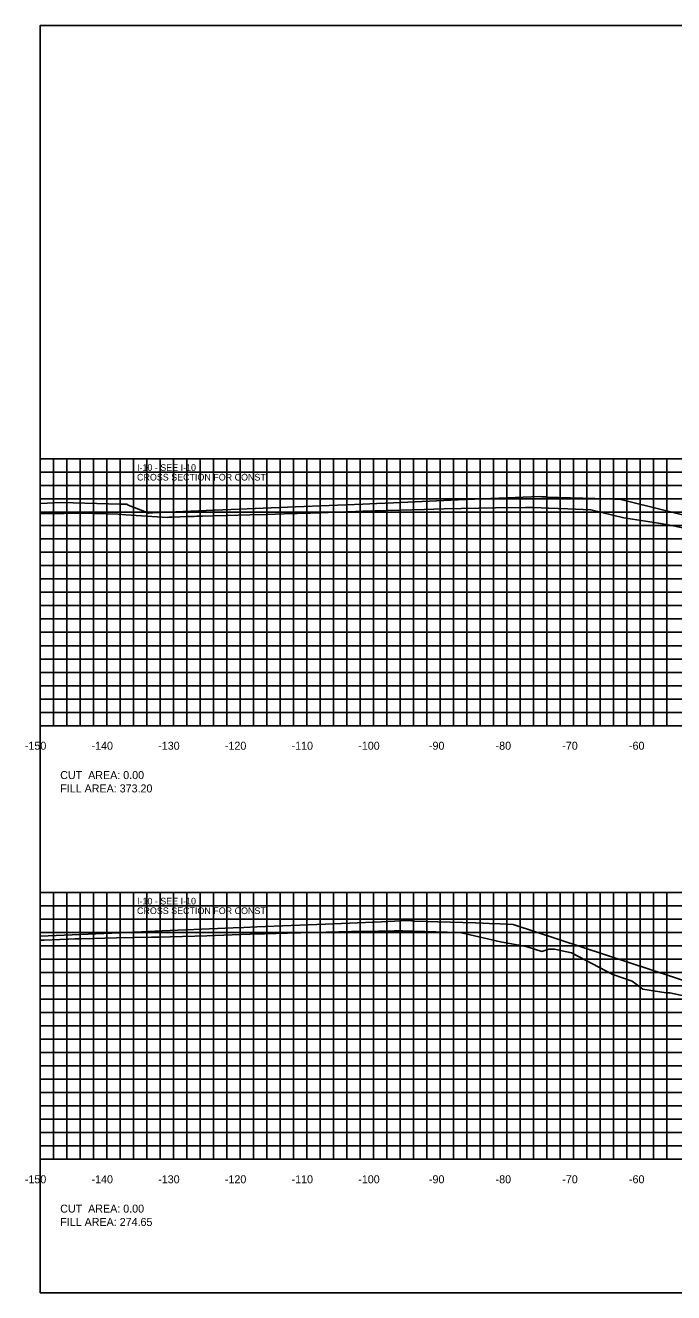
# Model space of a CAD drawing. Extents: x 1797652 to 1804145, y 245981 to 250269.
# Drawn here: x 1802818.8 to 1802916, y 250079.4 to 250269.4 of the extents above; entities that cross this region are included whole.
import ezdxf

# ---------------------------------------------------------------- set-up
doc = ezdxf.new("R2010")
doc.units = 0
for name, color, linetype in [('10', 7, 'Continuous'), ('3', 7, 'Continuous'), ('60', 7, 'Continuous'), ('ANNO-TXT', 7, 'Continuous'), ('CL-CNST', 7, 'Continuous'), ('Level 62', 7, 'Continuous'), ('M-ROADS', 7, 'Continuous')]:
    doc.layers.add(name, color=color, linetype=linetype)

msp = doc.modelspace()

# ---------------------------------------------------------------- linework, layer by layer
msp.add_lwpolyline([(1802821, 250079.43), (1803121, 250079.43), (1803121, 250269.43), (1802821, 250269.43)], close=True)
at = {"layer": '60'}
for p, q in [((1802820.94, 250204.43), (1802821, 250204.43)), ((1802821, 250164.43), (1802821, 250204.43)), ((1802820.94, 250194.43), (1802821, 250194.43)), ((1802820.94, 250184.43), (1802821, 250184.43)), ((1802820.94, 250174.43), (1802821, 250174.43)), ((1802820.94, 250164.43), (1802821, 250164.43)), ((1802821, 250164.43), (1803121, 250164.43)), ((1802821, 250164.37), (1802821, 250164.43)), ((1802831, 250164.37), (1802831, 250164.43)), ((1802841, 250164.37), (1802841, 250164.43)), ((1802851, 250164.37), (1802851, 250164.43)), ((1802861, 250164.37), (1802861, 250164.43)), ((1802871, 250164.37), (1802871, 250164.43)), ((1802881, 250164.37), (1802881, 250164.43)), ((1802891, 250164.37), (1802891, 250164.43)), ((1802901, 250164.37), (1802901, 250164.43)), ((1802911, 250164.37), (1802911, 250164.43)), ((1802820.94, 250139.43), (1802821, 250139.43)), ((1802821, 250099.43), (1802821, 250139.43)), ((1802820.94, 250129.43), (1802821, 250129.43)), ((1802820.94, 250119.43), (1802821, 250119.43)), ((1802820.94, 250109.43), (1802821, 250109.43)), ((1802820.94, 250099.43), (1802821, 250099.43)), ((1802821, 250099.43), (1803121, 250099.43)), ((1802821, 250099.37), (1802821, 250099.43)), ((1802831, 250099.37), (1802831, 250099.43)), ((1802841, 250099.37), (1802841, 250099.43)), ((1802851, 250099.37), (1802851, 250099.43)), ((1802861, 250099.37), (1802861, 250099.43)), ((1802871, 250099.37), (1802871, 250099.43)), ((1802881, 250099.37), (1802881, 250099.43)), ((1802891, 250099.37), (1802891, 250099.43)), ((1802901, 250099.37), (1802901, 250099.43)), ((1802911, 250099.37), (1802911, 250099.43))]:
    msp.add_line(p, q, dxfattribs=at)
at = {"layer": 'CL-CNST'}
for points in [[(1802821, 250197.76), (1802822.02, 250197.81), (1802824.18, 250197.9), (1802833, 250197.66), (1802833.97, 250197.64), (1802834.18, 250197.52), (1802837.3, 250196.32), (1802837.9, 250196.35), (1802845.9, 250196.69), (1802847.08, 250196.74), (1802847.19, 250196.74), (1802859.28, 250197.25), (1802869.39, 250197.67), (1802871.48, 250197.76), (1802873.97, 250197.86), (1802883.68, 250198.27), (1802887.34, 250198.42), (1802895.88, 250198.78), (1802896.25, 250198.76), (1802896.89, 250198.74), (1802896.93, 250198.7), (1802896.95, 250198.68), (1802900.54, 250198.58), (1802906.05, 250198.43), (1802907.18, 250198.39), (1802908.08, 250198.35), (1802928.03, 250193.38)], [(1802821, 250132.88), (1802827, 250133.14), (1802834.09, 250133.44), (1802839.28, 250133.66), (1802849.92, 250134.11), (1802851.54, 250134.17), (1802853.51, 250134.26), (1802863.8, 250134.69), (1802872.2, 250135.05), (1802876.07, 250135.21), (1802876.73, 250135.18), (1802877.09, 250135.17), (1802877.12, 250135.13), (1802877.14, 250135.11), (1802880.65, 250135.02), (1802886.29, 250134.87), (1802887.43, 250134.83), (1802888.33, 250134.79), (1802889.97, 250134.72), (1802891.91, 250134.64), (1802926.35, 250123.32), (1802933.6, 250120.94)]]:
    msp.add_lwpolyline(points, dxfattribs=at)
at = {"layer": 'Level 62'}
for p, q in [((1802821, 250204.43), (1803121, 250204.43)), ((1802821, 250164.43), (1802821, 250204.43)), ((1802823, 250164.43), (1802823, 250204.43)), ((1802825, 250164.43), (1802825, 250204.43)), ((1802827, 250164.43), (1802827, 250204.43)), ((1802829, 250164.43), (1802829, 250204.43)), ((1802831, 250164.43), (1802831, 250204.43)), ((1802833, 250164.43), (1802833, 250204.43)), ((1802835, 250164.43), (1802835, 250204.43)), ((1802837, 250164.43), (1802837, 250204.43)), ((1802839, 250164.43), (1802839, 250204.43)), ((1802841, 250164.43), (1802841, 250204.43)), ((1802843, 250164.43), (1802843, 250204.43)), ((1802845, 250164.43), (1802845, 250204.43)), ((1802847, 250164.43), (1802847, 250204.43)), ((1802849, 250164.43), (1802849, 250204.43)), ((1802851, 250164.43), (1802851, 250204.43)), ((1802853, 250164.43), (1802853, 250204.43)), ((1802855, 250164.43), (1802855, 250204.43)), ((1802857, 250164.43), (1802857, 250204.43)), ((1802859, 250164.43), (1802859, 250204.43)), ((1802861, 250164.43), (1802861, 250204.43)), ((1802863, 250164.43), (1802863, 250204.43)), ((1802865, 250164.43), (1802865, 250204.43)), ((1802867, 250164.43), (1802867, 250204.43)), ((1802869, 250164.43), (1802869, 250204.43)), ((1802871, 250164.43), (1802871, 250204.43)), ((1802873, 250164.43), (1802873, 250204.43)), ((1802875, 250164.43), (1802875, 250204.43)), ((1802877, 250164.43), (1802877, 250204.43)), ((1802879, 250164.43), (1802879, 250204.43)), ((1802881, 250164.43), (1802881, 250204.43)), ((1802883, 250164.43), (1802883, 250204.43)), ((1802885, 250164.43), (1802885, 250204.43)), ((1802887, 250164.43), (1802887, 250204.43)), ((1802889, 250164.43), (1802889, 250204.43)), ((1802891, 250164.43), (1802891, 250204.43)), ((1802893, 250164.43), (1802893, 250204.43)), ((1802895, 250164.43), (1802895, 250204.43)), ((1802897, 250164.43), (1802897, 250204.43)), ((1802899, 250164.43), (1802899, 250204.43)), ((1802901, 250164.43), (1802901, 250204.43)), ((1802903, 250164.43), (1802903, 250204.43)), ((1802905, 250164.43), (1802905, 250204.43)), ((1802907, 250164.43), (1802907, 250204.43)), ((1802909, 250164.43), (1802909, 250204.43)), ((1802911, 250164.43), (1802911, 250204.43)), ((1802913, 250164.43), (1802913, 250204.43)), ((1802915, 250164.43), (1802915, 250204.43)), ((1802821, 250202.43), (1803121, 250202.43)), ((1802821, 250200.43), (1803121, 250200.43)), ((1802821, 250198.43), (1803121, 250198.43)), ((1802821, 250196.43), (1803121, 250196.43)), ((1802821, 250194.43), (1803121, 250194.43)), ((1802821, 250192.43), (1803121, 250192.43)), ((1802821, 250190.43), (1803121, 250190.43)), ((1802821, 250188.43), (1803121, 250188.43)), ((1802821, 250186.43), (1803121, 250186.43)), ((1802821, 250184.43), (1803121, 250184.43)), ((1802821, 250182.43), (1803121, 250182.43)), ((1802821, 250180.43), (1803121, 250180.43)), ((1802821, 250178.43), (1803121, 250178.43)), ((1802821, 250176.43), (1803121, 250176.43)), ((1802821, 250174.43), (1803121, 250174.43)), ((1802821, 250172.43), (1803121, 250172.43)), ((1802821, 250170.43), (1803121, 250170.43)), ((1802821, 250168.43), (1803121, 250168.43)), ((1802821, 250166.43), (1803121, 250166.43)), ((1802821, 250164.43), (1803121, 250164.43)), ((1802821, 250139.43), (1803121, 250139.43)), ((1802821, 250099.43), (1802821, 250139.43)), ((1802823, 250099.43), (1802823, 250139.43)), ((1802825, 250099.43), (1802825, 250139.43)), ((1802827, 250099.43), (1802827, 250139.43)), ((1802829, 250099.43), (1802829, 250139.43)), ((1802831, 250099.43), (1802831, 250139.43)), ((1802833, 250099.43), (1802833, 250139.43)), ((1802835, 250099.43), (1802835, 250139.43)), ((1802837, 250099.43), (1802837, 250139.43)), ((1802839, 250099.43), (1802839, 250139.43)), ((1802841, 250099.43), (1802841, 250139.43)), ((1802843, 250099.43), (1802843, 250139.43)), ((1802845, 250099.43), (1802845, 250139.43)), ((1802847, 250099.43), (1802847, 250139.43)), ((1802849, 250099.43), (1802849, 250139.43)), ((1802851, 250099.43), (1802851, 250139.43)), ((1802853, 250099.43), (1802853, 250139.43)), ((1802855, 250099.43), (1802855, 250139.43)), ((1802857, 250099.43), (1802857, 250139.43)), ((1802859, 250099.43), (1802859, 250139.43)), ((1802861, 250099.43), (1802861, 250139.43)), ((1802863, 250099.43), (1802863, 250139.43)), ((1802865, 250099.43), (1802865, 250139.43)), ((1802867, 250099.43), (1802867, 250139.43)), ((1802869, 250099.43), (1802869, 250139.43)), ((1802871, 250099.43), (1802871, 250139.43)), ((1802873, 250099.43), (1802873, 250139.43)), ((1802875, 250099.43), (1802875, 250139.43)), ((1802877, 250099.43), (1802877, 250139.43)), ((1802879, 250099.43), (1802879, 250139.43)), ((1802881, 250099.43), (1802881, 250139.43)), ((1802883, 250099.43), (1802883, 250139.43)), ((1802885, 250099.43), (1802885, 250139.43)), ((1802887, 250099.43), (1802887, 250139.43)), ((1802889, 250099.43), (1802889, 250139.43)), ((1802891, 250099.43), (1802891, 250139.43)), ((1802893, 250099.43), (1802893, 250139.43)), ((1802895, 250099.43), (1802895, 250139.43)), ((1802897, 250099.43), (1802897, 250139.43)), ((1802899, 250099.43), (1802899, 250139.43)), ((1802901, 250099.43), (1802901, 250139.43)), ((1802903, 250099.43), (1802903, 250139.43)), ((1802905, 250099.43), (1802905, 250139.43)), ((1802907, 250099.43), (1802907, 250139.43)), ((1802909, 250099.43), (1802909, 250139.43)), ((1802911, 250099.43), (1802911, 250139.43)), ((1802913, 250099.43), (1802913, 250139.43)), ((1802915, 250099.43), (1802915, 250139.43)), ((1802821, 250137.43), (1803121, 250137.43)), ((1802821, 250135.43), (1803121, 250135.43)), ((1802821, 250133.43), (1803121, 250133.43)), ((1802821, 250131.43), (1803121, 250131.43)), ((1802821, 250129.43), (1803121, 250129.43)), ((1802821, 250127.43), (1803121, 250127.43)), ((1802821, 250125.43), (1803121, 250125.43)), ((1802821, 250123.43), (1803121, 250123.43)), ((1802821, 250121.43), (1803121, 250121.43)), ((1802821, 250119.43), (1803121, 250119.43)), ((1802821, 250117.43), (1803121, 250117.43)), ((1802821, 250115.43), (1803121, 250115.43)), ((1802821, 250113.43), (1803121, 250113.43)), ((1802821, 250111.43), (1803121, 250111.43)), ((1802821, 250109.43), (1803121, 250109.43)), ((1802821, 250107.43), (1803121, 250107.43)), ((1802821, 250105.43), (1803121, 250105.43)), ((1802821, 250103.43), (1803121, 250103.43)), ((1802821, 250101.43), (1803121, 250101.43)), ((1802821, 250099.43), (1803121, 250099.43))]:
    msp.add_line(p, q, dxfattribs=at)
at = {"layer": 'M-ROADS'}
for points in [[(1802821, 250196.21), (1802822.4, 250196.23), (1802824.61, 250196.27), (1802826.12, 250196.29), (1802827.01, 250196.3), (1802827.4, 250196.3), (1802830.89, 250196.19), (1802832.68, 250196.14), (1802833.82, 250196.07), (1802840.1, 250195.67), (1802840.28, 250195.68), (1802840.79, 250195.7), (1802843.19, 250195.78), (1802844.07, 250195.81), (1802844.51, 250195.83), (1802845.35, 250195.86), (1802848.89, 250195.95), (1802852.44, 250196.04), (1802855, 250196.11), (1802857.58, 250196.18), (1802861.52, 250196.31), (1802866.82, 250196.49), (1802868.29, 250196.54), (1802869.37, 250196.58), (1802878.63, 250196.86), (1802880.03, 250196.9), (1802881.57, 250196.95), (1802889.27, 250197.08), (1802893.77, 250197.15), (1802894.42, 250197.15), (1802895.04, 250197.14), (1802897.23, 250197.06), (1802900.13, 250196.95), (1802903.56, 250196.81), (1802905.24, 250196.41), (1802908.52, 250195.61), (1802913.72, 250194.81), (1802915.41, 250194.48), (1802918.6, 250193.86)], [(1802821, 250132.26), (1802821.59, 250132.28), (1802823.96, 250132.36), (1802825.01, 250132.42), (1802825.23, 250132.43), (1802826.17, 250132.46), (1802827.13, 250132.48), (1802832.45, 250132.62), (1802837.69, 250132.71), (1802838.85, 250132.74), (1802840.54, 250132.79), (1802846, 250132.95), (1802849.77, 250133.08), (1802852.48, 250133.17), (1802854.71, 250133.23), (1802858.08, 250133.32), (1802862.16, 250133.45), (1802863.88, 250133.48), (1802867.71, 250133.56), (1802871.75, 250133.65), (1802874.07, 250133.69), (1802874.41, 250133.69), (1802875.35, 250133.67), (1802883.66, 250133.45), (1802883.81, 250133.44), (1802883.91, 250133.44), (1802884.18, 250133.38), (1802890.03, 250132.03), (1802893.9, 250131.35), (1802896.23, 250130.6), (1802897.26, 250130.93), (1802897.71, 250130.93), (1802898.13, 250130.93), (1802900.68, 250130.38), (1802906.87, 250127.13), (1802909.77, 250126.14), (1802911.37, 250124.93), (1802914.89, 250124.4), (1802915.17, 250124.4), (1802915.42, 250124.4), (1802918.62, 250123.68)]]:
    msp.add_lwpolyline(points, dxfattribs=at)

# ---------------------------------------------------------------- texts
at = {"layer": '10'}
for s, p in [('-150', (1802818.7, 250160.83)), ('-140', (1802828.7, 250160.83)), ('-130', (1802838.7, 250160.83)), ('-120', (1802848.7, 250160.83)), ('-110', (1802858.7, 250160.83)), ('-100', (1802868.7, 250160.83)), ('-90', (1802879.3, 250160.83)), ('-80', (1802889.3, 250160.83)), ('-70', (1802899.3, 250160.83)), ('-60', (1802909.3, 250160.83)), ('-150', (1802818.7, 250095.83)), ('-140', (1802828.7, 250095.83)), ('-130', (1802838.7, 250095.83)), ('-120', (1802848.7, 250095.83)), ('-110', (1802858.7, 250095.83)), ('-100', (1802868.7, 250095.83)), ('-90', (1802879.3, 250095.83)), ('-80', (1802889.3, 250095.83)), ('-70', (1802899.3, 250095.83)), ('-60', (1802909.3, 250095.83))]:
    msp.add_text(s, height=1.2, dxfattribs=at).set_placement(p)
at = {"layer": '3'}
for s, p in [('I-10 - SEE I-10', (1802835.52, 250202.63)), ('CROSS SECTION FOR CONST ', (1802835.52, 250201.19)), ('CROSS SECTION FOR CONST ', (1802835.52, 250136.19)), ('I-10 - SEE I-10', (1802835.52, 250137.63))]:
    msp.add_text(s, height=1, dxfattribs=at).set_placement(p)
at = {"layer": '60'}
for p in [(1802821, 250164.43), (1802821, 250099.43)]:
    msp.add_text('-', height=0.0001, dxfattribs=at).set_placement(p)
at = {"layer": 'ANNO-TXT'}
for s, p in [('CUT  AREA: 0.00', (1802824, 250156.43)), ('FILL AREA: 373.20', (1802824, 250154.43)), ('CUT  AREA: 0.00', (1802824, 250091.43)), ('FILL AREA: 274.65', (1802824, 250089.43))]:
    msp.add_text(s, height=1.2, dxfattribs=at).set_placement(p)

doc.saveas('drawing.dxf')
